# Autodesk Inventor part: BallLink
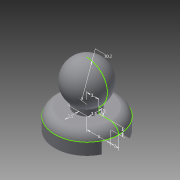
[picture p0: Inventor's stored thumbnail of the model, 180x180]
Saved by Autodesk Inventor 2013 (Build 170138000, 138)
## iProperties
Created: 2013-03
Part Number: BallLink
Material: Generic
Document SubType Name: Modeling
Designer: frankenteddy
Density: 1 g/cm^3
Author: frankenteddy
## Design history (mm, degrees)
sketch "Sketch1"
  geometry: L1 (0, -5.624)-(-3, -5.624); L2 (-3, -5.624)-(-3, -4.124); L3 (0, 5.1)-(0, -5.1); L4 (0, -4.124)-(0, -5.624); L5 (-3, -4.124)-(0, -4.124); L6 (0, -5.624)-(-6, -5.624); L7 (-6, -5.624)-(-6, -7.624); L8 (-6, -7.624)-(0, -7.624); L9 (0, -7.624)-(0, -5.624); L10 (-6, -7.624)-(-8, -7.624); A1 r 5.1 centre (0, 0) between (0, 5.1) and (0, -5.1); A2 r 2.668 centre (-5.401, -8.224) between (-6, -5.624) and (-8, -7.624); 2 further points
  constraints: 20 end point, 5 point on circle, 4 perpendicular, 3 parallel, 2 centre point, 2 horizontal, 2 point on line, 1 coincident, 1 midpoint
  dimensions: "d0" = 10.2 diameter of A1; "d3" = 1.5 distance of L1.end L2.end; "d4" = 3 distance of L2.end L5.end; "d7" = 6 distance of L8.end L7.end; "d8" = 2 distance of L7.end L6.end; "d9" = 2 distance of L7.end L10.end
revolve "Revolution2" stored, may be unused: angle "d10" = 90 deg
sketch "Sketch4"
  geometry: L1 (0, 0)-(8, 0); L2 (7.194, 3.5)-(-7.194, 3.5); L3 (7.194, -3.5)-(-7.194, -3.5); C1 r 4.807 at (0, 0); A1 r 8 centre (0, 0) between (8, 0) and (7.194, 3.5) reference; A2 r 8 centre (0, 0) between (-7.194, 3.5) and (-7.194, -3.5)
  constraints: 6 end point, 5 point on circle, 2 centre point, 2 parallel, 1 coincident, 1 concentric, 1 horizontal
  dimensions: "d46" = 3.5 distance between parallel lines of L2 L1; "d48" = 3.5 distance between parallel lines of L3 L1
extrude "Extrusion5" join sketch "Sketch4" distance "d53" = 3; taper "d54" = 0 deg
body "Solid2"
